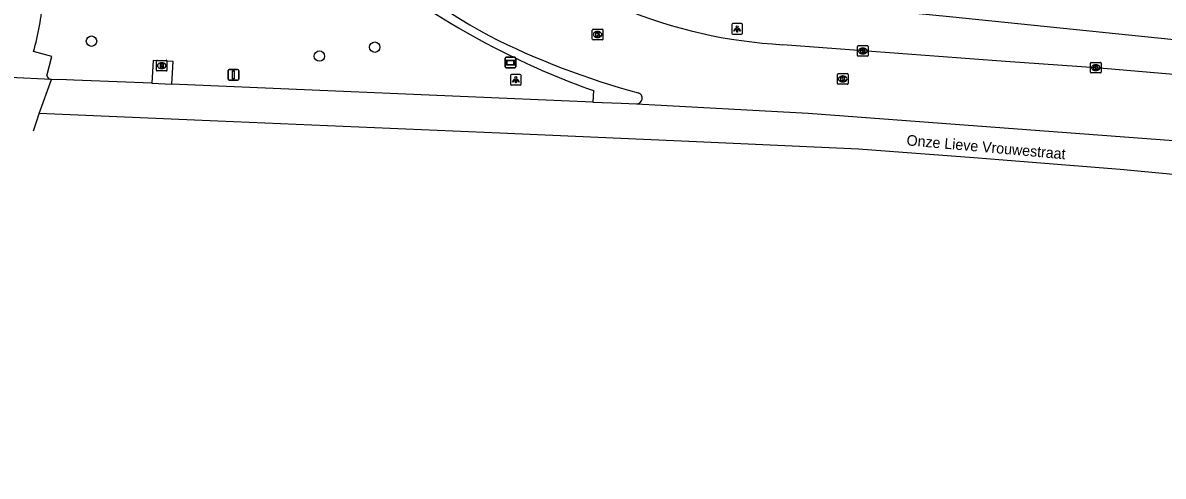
# Model space of a CAD drawing. Extents: x 161761 to 162722, y 384793 to 385405.
# Drawn here: x 161827 to 161934.4, y 384835.7 to 384878.3 of the extents above; entities that cross this region are included whole.
import ezdxf

# ---------------------------------------------------------------- set-up
doc = ezdxf.new("R2010")
doc.units = 0
for name, color, linetype in [('IMGEO_Berm_gesloten', 7, 'Continuous'), ('IMGEO_Berm_groen', 7, 'Continuous'), ('IMGEO_Boom', 7, 'Continuous'), ('IMGEO_Brandkraan', 7, 'Continuous'), ('IMGEO_Fietspad_open', 7, 'Continuous'), ('IMGEO_Kolk', 7, 'Continuous'), ('IMGEO_Lichtpunt', 7, 'Continuous'), ('IMGEO_Openbare_ruimte_label', 7, 'Continuous'), ('IMGEO_Rijbaan_lokaal_open', 7, 'Continuous'), ('IMGEO_Rijbaan_regionaal_gesloten', 7, 'Continuous'), ('IMGEO_Verkeersbord', 7, 'Continuous'), ('IMGEO_Verkeersbordpaal', 7, 'Continuous'), ('IMGEO_Voetpad_open', 7, 'Continuous')]:
    doc.layers.add(name, color=color, linetype=linetype)

msp = doc.modelspace()

# ---------------------------------------------------------------- linework, layer by layer
at = {"layer": 'IMGEO_Berm_gesloten'}
msp.add_lwpolyline([(161880.71, 384871.94), (161880.65, 384870.85)], dxfattribs=at)
for centre, radius, start, end in [((161908.71, 384947.96), 81.08, 232.3709, 243.2705), ((161904.94, 384940.73), 72.93, 243.365, 250.596)]:
    msp.add_arc(centre, radius, start, end, dxfattribs=at)
at = {"layer": 'IMGEO_Berm_groen'}
msp.add_lwpolyline([(161841.02, 384872.55), (161841.14, 384874.68), (161839.27, 384874.75), (161839.14, 384872.62)], dxfattribs=at)
at = {"layer": 'IMGEO_Boom'}
for centre in [(161833.45, 384876.58), (161860.12, 384876.02), (161854.91, 384875.18)]:
    msp.add_circle(centre, 0.489, dxfattribs=at)
at = {"layer": 'IMGEO_Brandkraan'}
for p, q in [((161839.56, 384873.86), (161839.56, 384874.71)), ((161839.64, 384874.78), (161840.49, 384874.78)), ((161840.56, 384874.71), (161840.56, 384873.86)), ((161840.49, 384873.78), (161839.64, 384873.78)), ((161840.05, 384874.56), (161840.08, 384874.56)), ((161840.07, 384874), (161840.05, 384874))]:
    msp.add_line(p, q, dxfattribs=at)
for points in [[(161839.56, 384873.86), (161839.56, 384874.71)], [(161839.64, 384874.78), (161840.49, 384874.78)], [(161840.56, 384874.71), (161840.56, 384873.86)], [(161840.49, 384873.78), (161839.64, 384873.78)], [(161839.91, 384874.48), (161839.91, 384874.08), (161840.12, 384874.08)], [(161840.14, 384874.48), (161839.91, 384874.48)], [(161840.09, 384874.4), (161840.03, 384874.4), (161840.03, 384874.33)], [(161840.03, 384874.33), (161840.09, 384874.33)], [(161840.1, 384874.25), (161840.03, 384874.25), (161840.03, 384874.17)], [(161840.03, 384874.17), (161840.1, 384874.17)]]:
    msp.add_lwpolyline(points, dxfattribs=at)
for centre, radius, start, end in [((161839.64, 384874.71), 0.0765, 91.552, 178.448), ((161839.64, 384874.71), 0.0765, 91.552, 178.448), ((161840.49, 384874.71), 0.0765, 1.552, 88.448), ((161840.49, 384874.71), 0.0765, 1.552, 88.448), ((161839.64, 384873.86), 0.0765, 181.552, 268.448), ((161839.64, 384873.86), 0.0765, 181.552, 268.448), ((161840.09, 384874.36), 0.0379, 267.8285, 90.9355), ((161840.1, 384874.21), 0.0404, 269.8759, 90.5077), ((161840.13, 384874.33), 0.251, 268.6676, 293.5347), ((161840.15, 384874.34), 0.145, 59.4692, 91.5367), ((161840.17, 384874.38), 0.0922, 285.5137, 58.1501), ((161840.17, 384874.19), 0.105, 301.3115, 78.989), ((161840.49, 384873.86), 0.0765, 271.552, 358.448), ((161840.49, 384873.86), 0.0765, 271.552, 358.448)]:
    msp.add_arc(centre, radius, start, end, dxfattribs=at)
for centre, major_axis, ratio, start_param, end_param in [((161840.05, 384874.28), (-0.387, 0.002), 0.722429, 4.712389, 7.853982), ((161840.07, 384874.28), (-0.39, 0.002), 0.717154, 1.570796, 4.712389)]:
    msp.add_ellipse(centre, major_axis=major_axis, ratio=ratio, start_param=start_param, end_param=end_param, dxfattribs=at)
at = {"layer": 'IMGEO_Fietspad_open'}
msp.add_lwpolyline([(162087.85, 384861.72), (162070.85, 384863.31), (162058.33, 384864.51), (162006.51, 384869.45), (161914.24, 384878.87), (161906.24, 384879.67)], dxfattribs=at)
at = {"layer": 'IMGEO_Kolk'}
for p, q in [((161880.61, 384876.78), (161880.61, 384877.63)), ((161880.69, 384877.71), (161881.54, 384877.71)), ((161881.1, 384877.49), (161881.12, 384877.49)), ((161881.12, 384876.93), (161881.1, 384876.93)), ((161881.61, 384877.63), (161881.61, 384876.78)), ((161881.54, 384876.71), (161880.69, 384876.71)), ((161905.59, 384875.23), (161905.59, 384876.08)), ((161905.66, 384876.16), (161906.51, 384876.16)), ((161906.07, 384875.94), (161906.1, 384875.94)), ((161906.59, 384876.08), (161906.59, 384875.23)), ((161906.51, 384875.16), (161905.66, 384875.16)), ((161906.1, 384875.38), (161906.07, 384875.38)), ((161927.52, 384873.66), (161927.52, 384874.52)), ((161927.6, 384874.59), (161928.45, 384874.59)), ((161928.45, 384873.59), (161927.6, 384873.59)), ((161928.01, 384874.37), (161928.04, 384874.37)), ((161928.03, 384873.81), (161928.01, 384873.81)), ((161928.52, 384874.52), (161928.52, 384873.66)), ((161903.69, 384872.6), (161903.69, 384873.46)), ((161903.77, 384873.53), (161904.62, 384873.53)), ((161904.62, 384872.53), (161903.77, 384872.53)), ((161904.18, 384873.31), (161904.21, 384873.31)), ((161904.2, 384872.75), (161904.18, 384872.75)), ((161904.7, 384873.46), (161904.7, 384872.6))]:
    msp.add_line(p, q, dxfattribs=at)
for points in [[(161880.61, 384876.78), (161880.61, 384877.63)], [(161880.69, 384877.71), (161881.54, 384877.71)], [(161880.93, 384877.41), (161881.06, 384877.41), (161881.06, 384877.26), (161881.18, 384877.41), (161881.35, 384877.41), (161881.2, 384877.26), (161881.36, 384877.01), (161881.2, 384877.01), (161881.12, 384877.17), (161881.06, 384877.11), (161881.06, 384877.01), (161880.93, 384877.01), (161880.93, 384877.41)], [(161881.61, 384877.63), (161881.61, 384876.78)], [(161881.54, 384876.71), (161880.69, 384876.71)], [(161905.59, 384875.23), (161905.59, 384876.08)], [(161905.66, 384876.16), (161906.51, 384876.16)], [(161905.91, 384875.86), (161906.03, 384875.86), (161906.03, 384875.71), (161906.16, 384875.86), (161906.32, 384875.86), (161906.18, 384875.71), (161906.33, 384875.46), (161906.18, 384875.46), (161906.09, 384875.62), (161906.03, 384875.56), (161906.03, 384875.46), (161905.91, 384875.46), (161905.91, 384875.86)], [(161906.59, 384876.08), (161906.59, 384875.23)], [(161906.51, 384875.16), (161905.66, 384875.16)], [(161927.52, 384873.66), (161927.52, 384874.52)], [(161927.6, 384874.59), (161928.45, 384874.59)], [(161928.45, 384873.59), (161927.6, 384873.59)], [(161927.84, 384874.29), (161927.97, 384874.29), (161927.97, 384874.14), (161928.1, 384874.29), (161928.26, 384874.29), (161928.12, 384874.14), (161928.27, 384873.89), (161928.12, 384873.89), (161928.03, 384874.05), (161927.97, 384873.99), (161927.97, 384873.89), (161927.84, 384873.89), (161927.84, 384874.29)], [(161928.52, 384874.52), (161928.52, 384873.66)], [(161903.69, 384872.6), (161903.69, 384873.46)], [(161903.77, 384873.53), (161904.62, 384873.53)], [(161904.62, 384872.53), (161903.77, 384872.53)], [(161904.01, 384873.23), (161904.14, 384873.23), (161904.14, 384873.08), (161904.27, 384873.23), (161904.43, 384873.23), (161904.29, 384873.08), (161904.44, 384872.83), (161904.29, 384872.83), (161904.2, 384872.99), (161904.14, 384872.93), (161904.14, 384872.83), (161904.01, 384872.83), (161904.01, 384873.23)], [(161904.7, 384873.46), (161904.7, 384872.6)]]:
    msp.add_lwpolyline(points, dxfattribs=at)
for centre, start, end in [((161880.69, 384877.63), 91.552, 178.448), ((161880.69, 384877.63), 91.552, 178.448), ((161880.69, 384876.78), 181.552, 268.448), ((161880.69, 384876.78), 181.552, 268.448), ((161881.54, 384877.63), 1.552, 88.448), ((161881.54, 384877.63), 1.552, 88.448), ((161881.54, 384876.78), 271.552, 358.448), ((161881.54, 384876.78), 271.552, 358.448), ((161905.66, 384876.08), 91.552, 178.448), ((161905.66, 384876.08), 91.552, 178.448), ((161906.51, 384876.08), 1.552, 88.448), ((161906.51, 384876.08), 1.552, 88.448), ((161905.66, 384875.23), 181.552, 268.448), ((161905.66, 384875.23), 181.552, 268.448), ((161906.51, 384875.23), 271.552, 358.448), ((161906.51, 384875.23), 271.552, 358.448), ((161927.6, 384874.51), 91.552, 178.448), ((161927.6, 384874.51), 91.552, 178.448), ((161927.6, 384873.67), 181.552, 268.448), ((161927.6, 384873.67), 181.552, 268.448), ((161928.45, 384874.51), 1.552, 88.448), ((161928.45, 384874.51), 1.552, 88.448), ((161928.45, 384873.67), 271.552, 358.448), ((161928.45, 384873.67), 271.552, 358.448), ((161903.77, 384873.45), 91.552, 178.448), ((161903.77, 384873.45), 91.552, 178.448), ((161903.77, 384872.6), 181.552, 268.448), ((161903.77, 384872.6), 181.552, 268.448), ((161904.62, 384873.45), 1.552, 88.448), ((161904.62, 384873.45), 1.552, 88.448), ((161904.62, 384872.6), 271.552, 358.448), ((161904.62, 384872.6), 271.552, 358.448)]:
    msp.add_arc(centre, 0.0765, start, end, dxfattribs=at)
for centre, major_axis, ratio, start_param, end_param in [((161881.1, 384877.21), (-0.387, 0.002), 0.722429, 4.712389, 7.853982), ((161881.12, 384877.21), (-0.39, 0.002), 0.717154, 1.570796, 4.712389), ((161906.07, 384875.66), (-0.387, 0.002), 0.722429, 4.712389, 7.853982), ((161906.1, 384875.66), (-0.39, 0.002), 0.717154, 1.570796, 4.712389), ((161928.01, 384874.09), (-0.387, 0.002), 0.722429, 4.712389, 7.853982), ((161928.03, 384874.09), (-0.39, 0.002), 0.717154, 1.570796, 4.712389), ((161904.18, 384873.03), (-0.387, 0.002), 0.722429, 4.712389, 7.853982), ((161904.21, 384873.03), (-0.39, 0.002), 0.717154, 1.570796, 4.712389)]:
    msp.add_ellipse(centre, major_axis=major_axis, ratio=ratio, start_param=start_param, end_param=end_param, dxfattribs=at)
at = {"layer": 'IMGEO_Lichtpunt'}
for p, q in [((161893.75, 384878.14), (161893.75, 384877.33)), ((161893.75, 384878.14), (161893.75, 384877.33)), ((161894.65, 384878.23), (161893.85, 384878.23)), ((161894.65, 384878.23), (161893.85, 384878.23)), ((161894.75, 384877.33), (161894.75, 384878.14)), ((161894.75, 384877.33), (161894.75, 384878.14)), ((161893.85, 384877.23), (161894.65, 384877.23)), ((161893.85, 384877.23), (161894.65, 384877.23)), ((161872.91, 384873.36), (161872.91, 384872.55)), ((161872.91, 384873.36), (161872.91, 384872.55)), ((161873.81, 384873.46), (161873, 384873.46)), ((161873.81, 384873.46), (161873, 384873.46)), ((161873.9, 384872.55), (161873.9, 384873.36)), ((161873.9, 384872.55), (161873.9, 384873.36)), ((161873, 384872.46), (161873.81, 384872.46)), ((161873, 384872.46), (161873.81, 384872.46))]:
    msp.add_line(p, q, dxfattribs=at)
for points in [[(161894.13, 384877.8), (161894.17, 384877.77), (161893.98, 384877.51), (161893.94, 384877.54), (161894.13, 384877.8)], [(161894.23, 384877.75), (161894.28, 384877.75), (161894.28, 384877.43), (161894.23, 384877.43), (161894.23, 384877.75)], [(161894.34, 384877.77), (161894.38, 384877.8), (161894.56, 384877.54), (161894.53, 384877.51), (161894.34, 384877.77)], [(161873.28, 384873.02), (161873.32, 384873), (161873.13, 384872.73), (161873.09, 384872.76), (161873.28, 384873.02)], [(161873.38, 384872.98), (161873.43, 384872.98), (161873.43, 384872.65), (161873.38, 384872.65), (161873.38, 384872.98)], [(161873.49, 384873), (161873.53, 384873.02), (161873.72, 384872.76), (161873.68, 384872.73), (161873.49, 384873)]]:
    msp.add_lwpolyline(points, dxfattribs=at)
for centre in [(161894.25, 384877.93), (161873.41, 384873.16)]:
    msp.add_circle(centre, 0.0994, dxfattribs=at)
for centre, start, end in [((161893.85, 384878.14), 90, 180), ((161893.85, 384878.14), 90, 180), ((161894.65, 384878.14), 0, 90), ((161894.65, 384878.14), 0, 90), ((161893.85, 384877.33), 180, 270), ((161893.85, 384877.33), 180, 270), ((161894.65, 384877.33), 270, 0), ((161894.65, 384877.33), 270, 360), ((161873, 384873.36), 90, 180), ((161873, 384873.36), 90, 180), ((161873, 384872.55), 180, 270), ((161873, 384872.55), 180, 270), ((161873.81, 384873.36), 0, 90), ((161873.81, 384873.36), 0, 90), ((161873.81, 384872.55), 270, 0), ((161873.81, 384872.55), 270, 360)]:
    msp.add_arc(centre, 0.0946, start, end, dxfattribs=at)
at = {"layer": 'IMGEO_Rijbaan_lokaal_open'}
msp.add_lwpolyline([(162015.56, 384865.32), (162012.89, 384865.62), (161993.71, 384867.66), (161971.83, 384869.89), (161969.95, 384870.08), (161949.95, 384872.11), (161939.02, 384873.12), (161928.02, 384874.09), (161919.53, 384874.68), (161906.09, 384875.66), (161898.54, 384876.25)], dxfattribs=at)
for centre, radius, start, end in [((161910.34, 384948.65), 81.71, 218.2725, 241.1078), ((161901.15, 384922.77), 46.59, 247.6945, 266.7853), ((161904.66, 384944.41), 75.32, 243.3312, 254.8239), ((161884.78, 384871.22), 0.528, 269.5476, 72.0508)]:
    msp.add_arc(centre, radius, start, end, dxfattribs=at)
at = {"layer": 'IMGEO_Rijbaan_regionaal_gesloten'}
for points in [[(161829.68, 384872.97), (161825.76, 384873.17), (161825.55, 384873.18), (161824.96, 384873.2)], [(161828.53, 384869.77), (161829.68, 384872.97)], [(161839.14, 384872.62), (161831.78, 384872.93), (161831.09, 384872.95), (161829.68, 384872.97)], [(161839.14, 384872.62), (161841.02, 384872.55)], [(161880.65, 384870.85), (161841.02, 384872.55)], [(161880.65, 384870.85), (161883.32, 384870.74), (161884.78, 384870.69)], [(161884.78, 384870.69), (161900.93, 384869.81), (161935.34, 384867.25), (161968.21, 384864.01), (162017.32, 384858.79), (162045.97, 384856.08), (162098.22, 384850.79)], [(161827.99, 384868.14), (161828.33, 384869.18), (161828.53, 384869.77)], [(162214.26, 384835.67), (162195.97, 384837.38), (162185.76, 384838.42), (162169.22, 384840.27), (162133.93, 384843.72), (162120.63, 384845.08), (162091.94, 384848.02), (162044.9, 384852.97), (162005.21, 384856.92), (161970.02, 384860.62), (161942.92, 384863.32), (161930.32, 384864.52), (161916.53, 384865.62), (161905.68, 384866.42), (161890.43, 384867.12), (161871.89, 384867.92), (161845.34, 384869.07), (161828.53, 384869.77), (161828.53, 384869.77)]]:
    msp.add_lwpolyline(points, dxfattribs=at)
at = {"layer": 'IMGEO_Verkeersbord'}
for p, q in [((161872.41, 384874.17), (161872.41, 384874.97)), ((161872.41, 384874.97), (161872.41, 384874.17)), ((161872.51, 384875.07), (161873.3, 384875.07)), ((161873.3, 384875.07), (161872.51, 384875.07)), ((161873.4, 384874.97), (161873.4, 384874.17)), ((161873.4, 384874.17), (161873.4, 384874.97)), ((161873.3, 384874.07), (161872.51, 384874.07)), ((161872.51, 384874.07), (161873.3, 384874.07))]:
    msp.add_line(p, q, dxfattribs=at)
for points in [[(161872.51, 384874.8), (161873.3, 384874.8), (161873.3, 384874.33), (161872.51, 384874.33), (161872.51, 384874.8)], [(161872.57, 384874.73), (161872.57, 384874.4), (161873.23, 384874.4), (161873.23, 384874.73), (161872.57, 384874.73)]]:
    msp.add_lwpolyline(points, dxfattribs=at)
for centre, start, end in [((161872.51, 384874.97), 90, 180), ((161872.51, 384874.97), 90, 180), ((161873.3, 384874.97), 0, 90), ((161873.3, 384874.97), 360, 90), ((161872.51, 384874.17), 180, 270), ((161872.51, 384874.17), 180, 270), ((161873.3, 384874.17), 270, 0), ((161873.3, 384874.17), 270, 0)]:
    msp.add_arc(centre, 0.1, start, end, dxfattribs=at)
at = {"layer": 'IMGEO_Verkeersbordpaal'}
for p, q in [((161846.33, 384873.02), (161846.33, 384873.82)), ((161846.33, 384873.82), (161846.33, 384873.02)), ((161846.43, 384873.92), (161847.21, 384873.92)), ((161847.21, 384873.92), (161846.43, 384873.92)), ((161847.31, 384873.82), (161847.31, 384873.02)), ((161847.31, 384873.02), (161847.31, 384873.82)), ((161847.21, 384872.92), (161846.43, 384872.92)), ((161846.43, 384872.92), (161847.21, 384872.92))]:
    msp.add_line(p, q, dxfattribs=at)
msp.add_lwpolyline([(161846.74, 384873.8), (161846.9, 384873.8), (161846.9, 384873.05), (161846.74, 384873.05), (161846.74, 384873.8)], dxfattribs=at)
for centre, start, end in [((161846.43, 384873.82), 90, 180), ((161846.43, 384873.82), 90, 180), ((161847.21, 384873.82), 0, 90), ((161847.21, 384873.82), 360, 90), ((161846.43, 384873.02), 180, 270), ((161846.43, 384873.02), 180, 270), ((161847.21, 384873.02), 270, 0), ((161847.21, 384873.02), 270, 0)]:
    msp.add_arc(centre, 0.1, start, end, dxfattribs=at)
at = {"layer": 'IMGEO_Voetpad_open'}
msp.add_lwpolyline([(161829.24, 384873.33), (161829.71, 384875.14), (161828, 384875.6)], dxfattribs=at)
for centre, radius, start, end in [((161803.39, 384882.58), 25.58, 344.1717, 355.3013), ((161829.75, 384873.5), 0.537, 198.4643, 262.999)]:
    msp.add_arc(centre, radius, start, end, dxfattribs=at)

# ---------------------------------------------------------------- texts
at = {"layer": 'IMGEO_Openbare_ruimte_label'}
msp.add_text('Onze Lieve Vrouwestraat', height=1, rotation=354.9508, dxfattribs=at).set_placement((161910.17, 384866.79))

doc.saveas('drawing.dxf')
